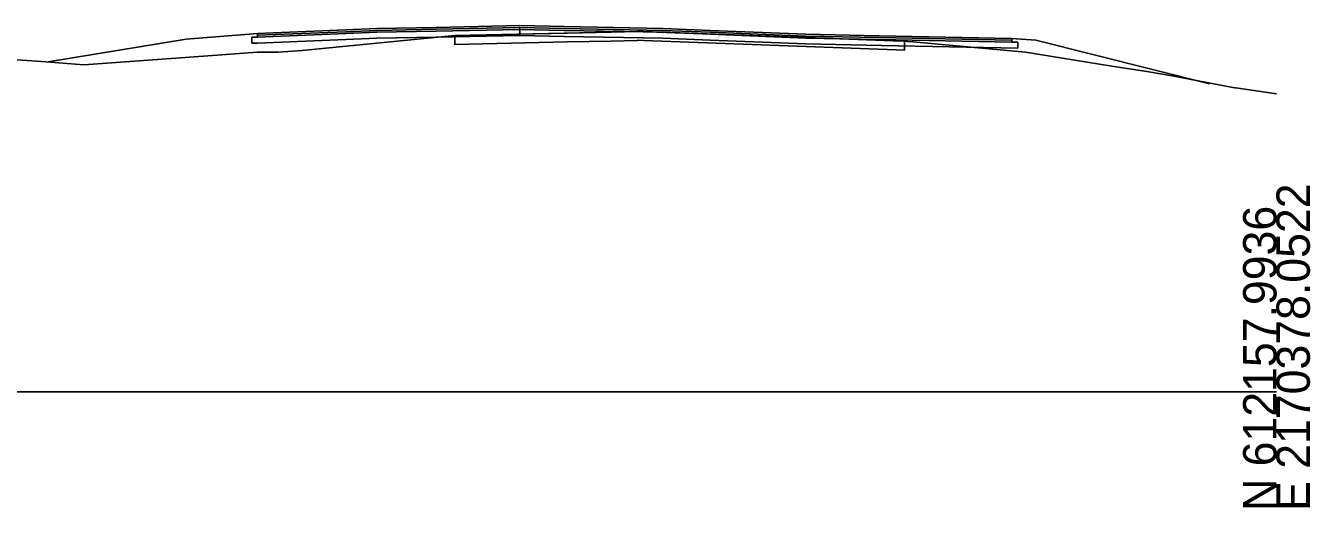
# Model space of a CAD drawing. Extents: x -26 to 1303, y -3010 to 12038.
# Drawn here: x 195 to 302.8, y 11490.3 to 11530.7 of the extents above; entities that cross this region are included whole.
import ezdxf

# ---------------------------------------------------------------- set-up
doc = ezdxf.new("R2010")
doc.units = 0
for name, color, linetype in [('RD_GPK_XS_Cell', 7, 'Continuous'), ('RD_XS_Base', 7, 'Continuous'), ('RD_XS_ExGround', 7, 'Continuous'), ('RD_XS_ExPaveRet', 7, 'Continuous'), ('RD_XS_Greenside', 7, 'Continuous'), ('RD_XS_Pave', 7, 'Continuous'), ('RD_XS_PaveOvlay_CP', 7, 'Continuous'), ('RD_XS_TieSlope', 7, 'Continuous')]:
    doc.layers.add(name, color=color, linetype=linetype)

msp = doc.modelspace()

# ---------------------------------------------------------------- linework, layer by layer
at = {"layer": 'RD_GPK_XS_Cell'}
msp.add_line((150, 11500), (300, 11500), dxfattribs=at)
at = {"layer": 'RD_XS_Base'}
for p, q in [((221.89, 11530.06), (224.49, 11530.17)), ((224.49, 11530.17), (229.46, 11530.27)), ((229.46, 11530.27), (236.49, 11530.41)), ((236.49, 11530.52), (236.49, 11530.57)), ((236.49, 11530.57), (236.49, 11530.37)), ((236.49, 11530.41), (236.49, 11530.52)), ((236.49, 11530.41), (236.49, 11530.41)), ((240.22, 11530.33), (236.49, 11530.41)), ((236.49, 11530.41), (236.49, 11530.41)), ((236.49, 11530.41), (236.49, 11530.26)), ((236.49, 11530.37), (236.49, 11529.91)), ((236.49, 11530.26), (236.49, 11529.91)), ((248.49, 11530.17), (240.22, 11530.33)), ((252.47, 11530.01), (248.49, 11530.17)), ((213.99, 11529.75), (214.37, 11529.76)), ((213.99, 11529.62), (213.99, 11529.75)), ((213.99, 11529.25), (213.99, 11529.62)), ((214.37, 11529.26), (213.99, 11529.25)), ((214.37, 11529.76), (214.49, 11529.77)), ((214.49, 11529.27), (214.37, 11529.26)), ((214.49, 11529.77), (221.89, 11530.06)), ((221.89, 11529.56), (214.49, 11529.27)), ((224.49, 11529.67), (221.89, 11529.56)), ((229.46, 11529.77), (224.49, 11529.67)), ((236.49, 11529.91), (229.46, 11529.77)), ((236.49, 11529.91), (240.22, 11529.83)), ((240.22, 11529.83), (248.49, 11529.67)), ((248.49, 11529.67), (252.47, 11529.51)), ((260.49, 11529.69), (252.47, 11530.01)), ((252.47, 11529.51), (260.49, 11529.19)), ((266.63, 11529.57), (260.49, 11529.69)), ((260.49, 11529.19), (266.82, 11529.06)), ((277.8, 11529.34), (266.63, 11529.57)), ((266.82, 11529.06), (278.3, 11528.83)), ((277.98, 11529.34), (277.8, 11529.34)), ((278.3, 11529.33), (277.98, 11529.34)), ((278.3, 11529.15), (278.3, 11529.33)), ((278.3, 11528.83), (278.3, 11529.15))]:
    msp.add_line(p, q, dxfattribs=at)
at = {"layer": 'RD_XS_ExGround'}
msp.add_lwpolyline([(184.86, 11528.52), (197.11, 11527.66), (199.91, 11527.45), (207.63, 11528), (211.08, 11528.26), (214.46, 11528.5), (216.21, 11528.5), (218.22, 11528.65), (231.03, 11529.89), (244.15, 11530.19), (246.42, 11530.25), (265.89, 11529.53), (268.09, 11529.45), (268.79, 11529.43), (269.03, 11529.41), (269.49, 11529.36), (278.93, 11528.5), (286.19, 11527.34), (289.13, 11526.87), (291.25, 11526.51), (296.34, 11525.54), (296.52, 11525.5), (296.6, 11525.5), (300, 11525.02)], dxfattribs=at)
at = {"layer": 'RD_XS_ExPaveRet'}
for p, q in [((246.42, 11530.25), (246.36, 11530.24)), ((268.79, 11529.43), (268.79, 11529.43))]:
    msp.add_line(p, q, dxfattribs=at)
for points in [[(268.79, 11529.43), (268.79, 11529.43), (268.79, 11529.33), (268.79, 11528.68), (268.79, 11528.68), (268.79, 11528.68), (268.79, 11528.68), (268.79, 11528.68), (268.09, 11528.7), (249.96, 11529.37), (246.87, 11529.48), (246.42, 11529.5), (246.36, 11529.49), (244.15, 11529.44), (240.48, 11529.36), (231.03, 11529.14), (231.03, 11529.14), (231.03, 11529.14), (231.03, 11529.68), (231.03, 11529.89), (231.03, 11529.89), (231.03, 11529.89), (240.48, 11530.11), (244.15, 11530.19), (246.36, 11530.24), (246.42, 11530.25), (246.87, 11530.23), (249.96, 11530.12), (268.09, 11529.45), (268.79, 11529.43), (268.79, 11529.43), (268.79, 11529.43), (268.79, 11529.43)], [(246.36, 11530.24), (244.15, 11530.19), (240.48, 11530.11), (231.03, 11529.89)], [(246.88, 11530.23), (246.87, 11530.23), (246.42, 11530.25)], [(267.82, 11529.46), (249.96, 11530.12), (246.88, 11530.23)], [(231.03, 11529.89), (231.03, 11529.68), (231.03, 11529.14), (240.48, 11529.36), (244.15, 11529.44), (246.36, 11529.49), (246.42, 11529.5), (246.87, 11529.48), (249.96, 11529.37), (268.09, 11528.7), (268.79, 11528.68), (268.79, 11528.68), (268.79, 11528.68), (268.79, 11528.68), (268.79, 11529.33), (268.79, 11529.43)], [(268.79, 11529.43), (268.79, 11529.43), (268.79, 11529.43), (268.09, 11529.45), (268.09, 11529.45), (267.82, 11529.46)]]:
    msp.add_lwpolyline(points, dxfattribs=at)
at = {"layer": 'RD_XS_Greenside'}
for p, q in [((208.49, 11529.6), (196.92, 11527.68)), ((279.8, 11529.5), (294.37, 11525.86))]:
    msp.add_line(p, q, dxfattribs=at)
at = {"layer": 'RD_XS_Pave'}
for p, q in [((221.89, 11530.38), (214.49, 11530.08)), ((221.89, 11530.22), (214.49, 11529.93)), ((214.49, 11529.93), (221.89, 11530.22)), ((224.49, 11530.48), (221.89, 11530.38)), ((224.49, 11530.33), (221.89, 11530.22)), ((221.89, 11530.22), (224.49, 11530.33)), ((221.89, 11530.06), (224.49, 11530.17)), ((229.46, 11530.58), (224.49, 11530.48)), ((229.46, 11530.43), (224.49, 11530.33)), ((224.49, 11530.33), (229.46, 11530.43)), ((224.49, 11530.17), (229.46, 11530.27)), ((236.49, 11530.73), (229.46, 11530.58)), ((236.49, 11530.57), (229.46, 11530.43)), ((229.46, 11530.43), (236.49, 11530.57)), ((229.46, 11530.27), (236.49, 11530.41)), ((240.22, 11530.65), (236.49, 11530.73)), ((236.49, 11530.52), (236.49, 11530.57)), ((236.49, 11530.57), (240.22, 11530.49)), ((240.22, 11530.49), (236.49, 11530.57)), ((236.49, 11530.57), (236.49, 11530.57)), ((236.49, 11530.57), (236.49, 11530.57)), ((236.49, 11530.57), (236.49, 11530.52)), ((236.49, 11530.41), (236.49, 11530.52)), ((236.49, 11530.52), (236.49, 11530.41)), ((236.49, 11530.41), (236.49, 11530.41)), ((236.49, 11530.41), (236.49, 11530.41)), ((236.49, 11530.41), (240.22, 11530.33)), ((248.49, 11530.49), (240.22, 11530.65)), ((240.22, 11530.49), (248.49, 11530.33)), ((248.49, 11530.33), (240.22, 11530.49)), ((240.22, 11530.33), (248.49, 11530.17)), ((252.47, 11530.33), (248.49, 11530.49)), ((248.49, 11530.33), (252.47, 11530.17)), ((252.47, 11530.17), (248.49, 11530.33)), ((248.49, 11530.17), (252.47, 11530.01)), ((260.49, 11530.01), (252.47, 11530.33)), ((252.47, 11530.17), (260.49, 11529.85)), ((260.49, 11529.85), (252.47, 11530.17)), ((214.49, 11530.08), (214.49, 11530.04)), ((214.49, 11529.77), (221.89, 11530.06)), ((214.49, 11530.04), (214.49, 11529.93)), ((214.49, 11529.93), (214.49, 11529.89)), ((214.49, 11529.89), (214.49, 11529.77)), ((252.47, 11530.01), (260.49, 11529.69)), ((266.63, 11529.88), (260.49, 11530.01)), ((260.49, 11529.85), (266.63, 11529.73)), ((266.63, 11529.73), (260.49, 11529.85)), ((260.49, 11529.69), (266.63, 11529.57)), ((277.8, 11529.66), (266.63, 11529.88)), ((266.63, 11529.73), (277.8, 11529.5)), ((277.8, 11529.5), (266.63, 11529.73)), ((266.63, 11529.57), (277.8, 11529.34)), ((277.8, 11529.6), (277.8, 11529.66)), ((277.8, 11529.5), (277.8, 11529.6)), ((277.8, 11529.44), (277.8, 11529.5)), ((277.8, 11529.34), (277.8, 11529.44))]:
    msp.add_line(p, q, dxfattribs=at)
at = {"layer": 'RD_XS_PaveOvlay_CP'}
for p, q in [((221.89, 11530.38), (214.49, 11530.08)), ((224.49, 11530.48), (221.89, 11530.38)), ((229.46, 11530.58), (224.49, 11530.48)), ((236.49, 11530.73), (229.46, 11530.58)), ((240.22, 11530.65), (236.49, 11530.73)), ((248.49, 11530.49), (240.22, 11530.65)), ((252.47, 11530.33), (248.49, 11530.49)), ((260.49, 11530.01), (252.47, 11530.33)), ((266.63, 11529.88), (260.49, 11530.01)), ((277.8, 11529.66), (266.63, 11529.88))]:
    msp.add_line(p, q, dxfattribs=at)
at = {"layer": 'RD_XS_TieSlope'}
for p, q in [((214.49, 11530.08), (208.49, 11529.6)), ((277.8, 11529.66), (279.8, 11529.5))]:
    msp.add_line(p, q, dxfattribs=at)

# ---------------------------------------------------------------- texts
at = {"layer": 'RD_GPK_XS_Cell'}
for s, p in [('E 2170378.0522', (302.8, 11490)), ('N 612157.9936', (300, 11490))]:
    msp.add_text(s, height=2.8, rotation=90, dxfattribs=at).set_placement(p)

doc.saveas('drawing.dxf')
